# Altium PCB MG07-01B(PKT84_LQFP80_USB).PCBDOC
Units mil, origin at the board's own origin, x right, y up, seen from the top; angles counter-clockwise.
Board outline 2755.91 x 2755.91 mil, 2 copper layers (Top Layer, Bottom Layer); 70 components, 99 nets, 341 pads, 159 vias.
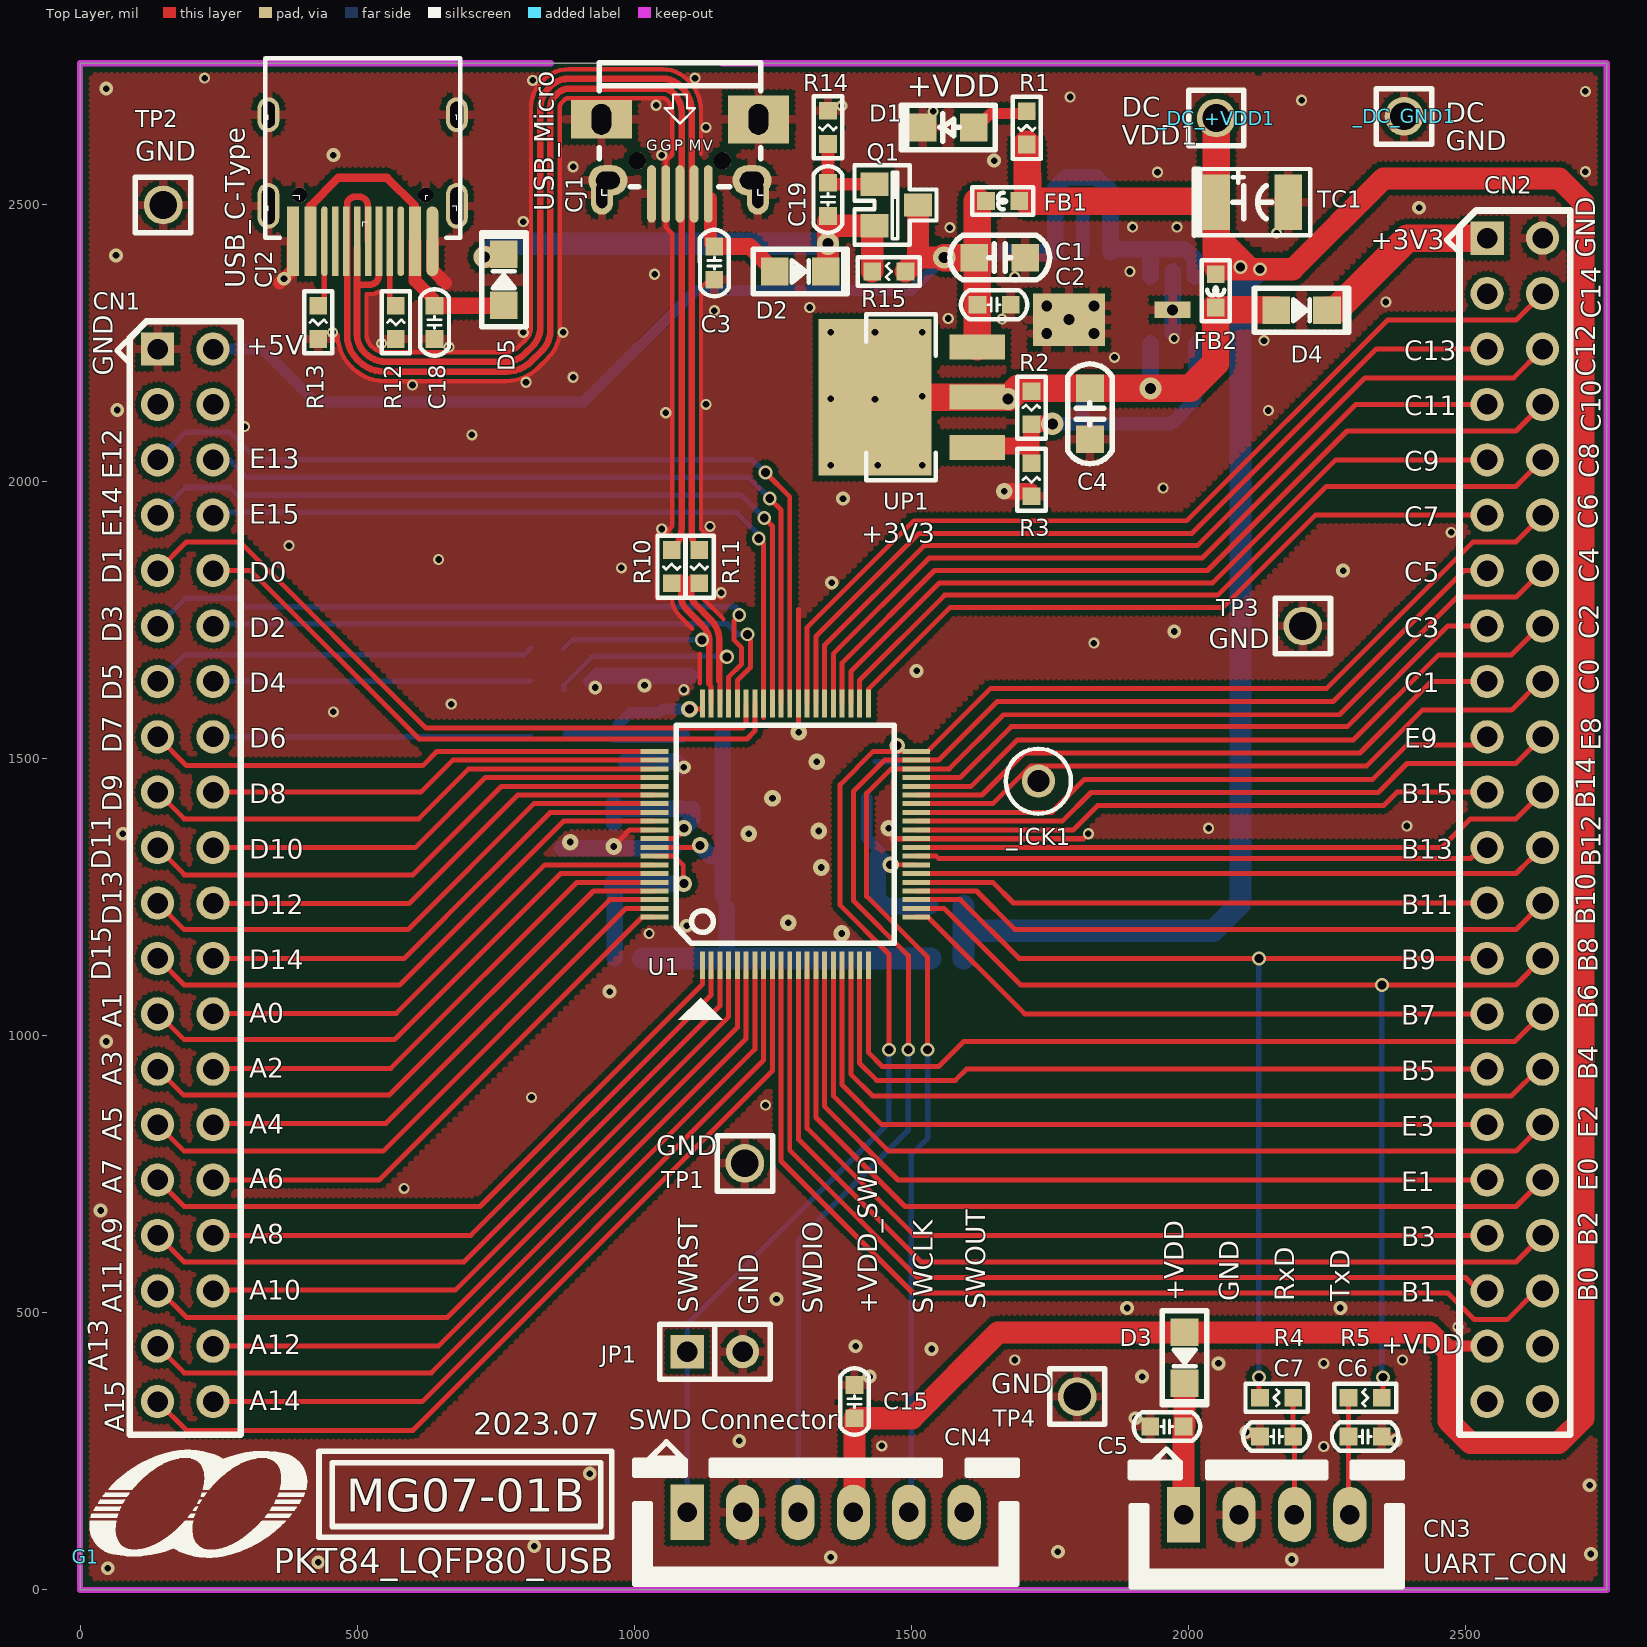
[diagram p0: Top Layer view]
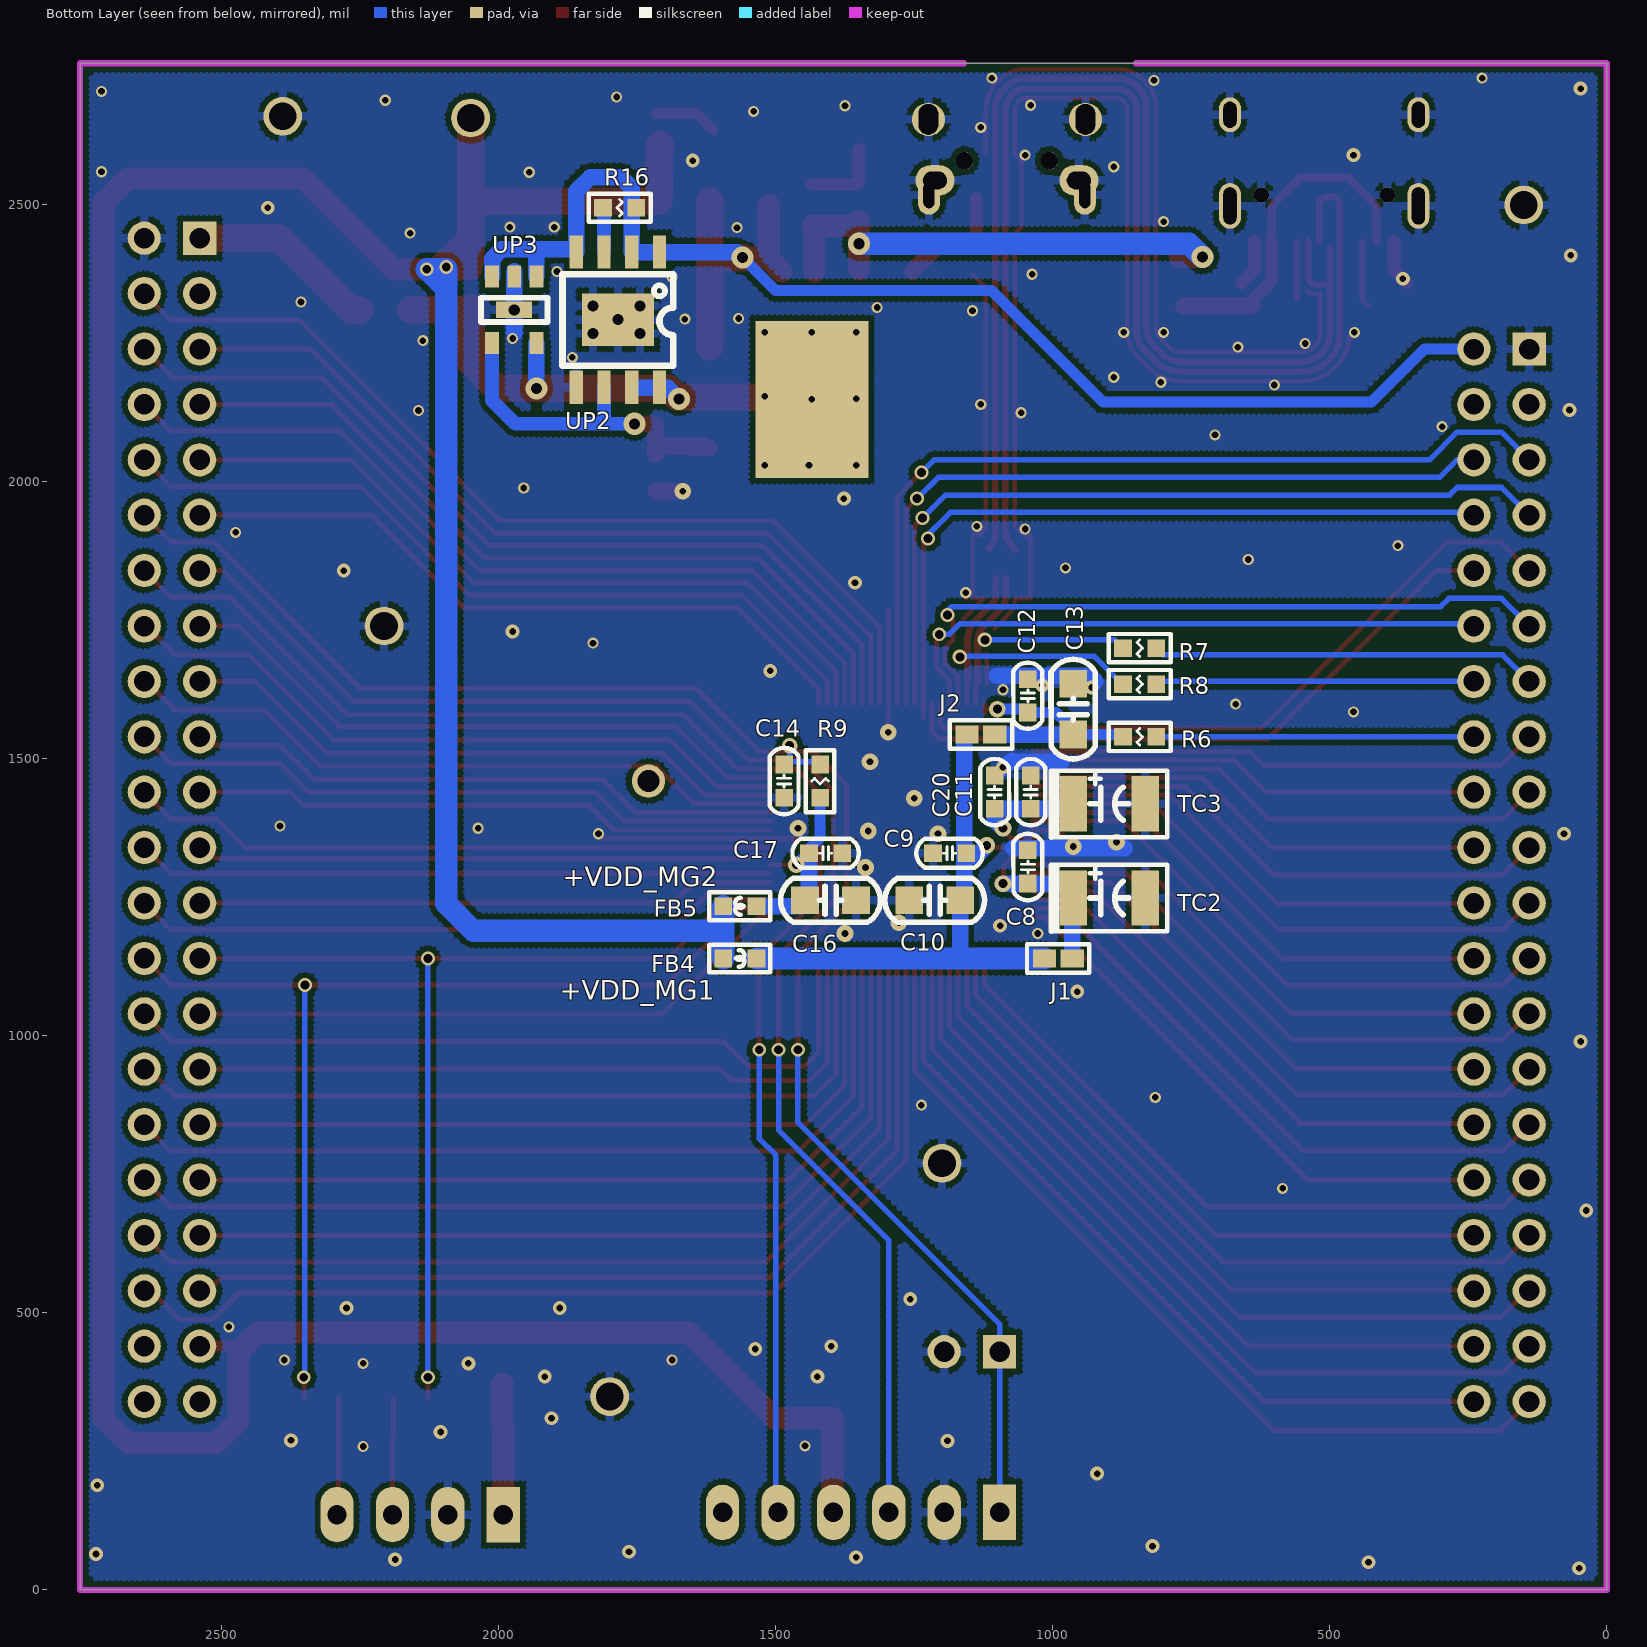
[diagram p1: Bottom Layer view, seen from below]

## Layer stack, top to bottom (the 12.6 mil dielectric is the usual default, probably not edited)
Top Layer: signal copper 1.4
Dielectric: dielectric 12.6, FR-4, Dk 4.8
Bottom Layer: signal copper 1.4

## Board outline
0,0 2755.91,0 2755.91,2755.91 0,2755.91

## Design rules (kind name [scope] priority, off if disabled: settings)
Clearance 10 [All] p1 off: gap=10
Clearance 7 [All] p2 off: gap=7
Clearance 6 [All] p3: gap=6
HoleSize [All] p1 off: absolutevalues=TRUE maxlimit=100 minlimit=1 maxpercent=80.000 minpercent=20.000
MinimumSolderMaskSliver [All] p1 off: minsoldermaskwidth=10
PolygonConnect +5V_USB [InNet('+5V_USB')] p1: connectstyle=Direct reliefconductorwidth=10 reliefentries=4 polygonreliefangle="90 Angle"
PolygonConnect via [isvia] p2: connectstyle=Direct reliefconductorwidth=10 reliefentries=4 polygonreliefangle="90 Angle"
PolygonConnect PolygonConnect_1 [All] p3: connectstyle=Relief reliefconductorwidth=15 reliefentries=4 polygonreliefangle="90 Angle"
RoomDefinition 02 [InComponentClass('02')] p1: confinementstyle=ConfineIn formatcopy=TRUE lockcomponents=FALSE outline -145,-65 2900,-65 2900,2850 -145,2850
RoomDefinition 01 [InComponentClass('01')] p2: confinementstyle=ConfineIn formatcopy=TRUE lockcomponents=FALSE outline -305,-15 2985,-15 2985,2795 -305,2795
RoutingVias [All] p1: holewidth=16 width=25 viastyle="Through Hole" minholewidth=16 minwidth=25 maxholewidth=28 maxwidth=50
SilkToSilkClearance [All] p1 off: silktosilkclearance=10
SilkscreenOverComponentPads [All] p1 off: minsilkscreentomaskgap=10
SolderMaskExpansion [All] p1: expansion=4
Width [All] p1: maxlimit=100 minlimit=6 preferedwidth=12
24 further rules are at their usual default settings.

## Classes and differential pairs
component class 02: _ICK1 C8 C9 C10 C11 C12 C13 C14 C15 C16 C17 C20 CN4 FB4 FB5 J1 J2 JP1 R6 R7 R8 R9 R10 R11 TC2 TC3 U1
component class 01: _DC_+VDD1 _DC_GND1 C1 C2 C3 C4 C5 C6 C7 C18 C19 CJ1 CJ2 CN1 CN2 CN3 D1 D2 D3 D4 D5 FB1 FB2 G1 Q1 R1 R2 R3 R4 R5 R12 R13 R14 R15 R16 TC1 TP1 TP2 TP3 TP4 UP1 UP2 UP3
net class MG_PE[0..15]: MG_PE0 MG_PE1 MG_PE2 MG_PE3 MG_PE8 MG_PE9 MG_PE12 MG_PE13 MG_PE14 MG_PE15
net class MG_PD[0..15]: MG_PD0 MG_PD1 MG_PD2 MG_PD3 MG_PD4 MG_PD5 MG_PD6 MG_PD7 MG_PD8 MG_PD9 MG_PD10 MG_PD11 MG_PD12 MG_PD13 MG_PD14 MG_PD15
net class MG_PC[0..14]: MG_PC0 MG_PC1 MG_PC2 MG_PC3 MG_PC4 MG_PC5 MG_PC6 MG_PC7 MG_PC8 MG_PC9 MG_PC10 MG_PC11 MG_PC12 MG_PC13 MG_PC14
net class MG_PB[0..15]: MG_PB0 MG_PB1 MG_PB2 MG_PB3 MG_PB4 MG_PB5 MG_PB6 MG_PB7 MG_PB8 MG_PB9 MG_PB10 MG_PB11 MG_PB12 MG_PB13 MG_PB14 MG_PB15
net class MG_PA[0..15]: MG_PA0 MG_PA1 MG_PA2 MG_PA3 MG_PA4 MG_PA5 MG_PA6 MG_PA7 MG_PA8 MG_PA9 MG_PA10 MG_PA11 MG_PA12 MG_PA13 MG_PA14 MG_PA15

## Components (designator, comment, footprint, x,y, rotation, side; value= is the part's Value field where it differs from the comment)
_DC_+VDD1 "+5V_DC" SIP1-50 2050.91,2657 r0 top
_DC_GND1 "GND" SIP1-50 2390,2660 r0 top
_ICK1 "TP-COIL" TPH60-COIL 1730,1460 r0 top
C1 "10uF/10v" C-0805 1660,2405 r0 top
C2 "0.1uF" C-0603 1650,2320 r0 top
C3 "1uF" C-0603 1145,2395 r270 top
C4 "10uF/10v" C-0805 1822.91,2123 r270 top
C5 "0.1uF" C-0603 1961.8,294.94 r180 top
C6 "47PF" C-0603 2319.8,276.94 r0 top
C7 "47PF" C-0603 2159.8,276.94 r180 top
C8 "0.1uF" C-0603 1045,1305 r90 bottom
C9 "0.1uF" C-0603 1186.2,1330 r0 bottom
C10 "10uF/10v" C-0805 1213.2,1245 r0 bottom
C11 "0.1uF" C-0603 1040,1440 r90 bottom
C12 "0.1uF" C-0603 1045,1614.06 r90 bottom
C13 "10uF/10v" C-0805 963.2,1590 r90 bottom
C14 "4.7uF" C-0603 1485,1460 r270 bottom
C15 "0.1uF" C-0603 1398,340 r90 top
C16 "10uF/10v" C-0805 1401.2,1245 r180 bottom
C17 "0.1uF" C-0603 1410,1330 r180 bottom
C18 "1uF" C-0603 640,2288 r270 top
C19 "0.1uF" C-0603 1350,2510 r90 top
C20 "1000pF" C-0603 1105,1440 r90 bottom
CJ1 "CJ-USB-Micro" USB5B-MICRO-7.5.X5.4P065 1134,2520 r180 top
CJ2 "CJ-USB3-C16P" USB16-C-C16P 510.08,2470 r180 top
CN1 "HEADER20X2-2.54-Female" HD20X2-P2.54 140,2240 r270 top locked
CN2 "HEADER22X2-2.54-Female" HD22X2-P2.54 2540,2440 r270 top locked
CN3 "SIP4-2.54mm" HD4-P2.54-Z12.4X5.7X7-UL 2142,136 r0 top
CN4 "SIP6-2.54mm" HD6-P2.54-UL 1346,140 r0 top
D1 "LED0805-Red" LED-0805 1565.32,2640 r270 top
D2 "B5817" D-0805 1300,2380 r90 top
D3 "B5817" D-0805 1993.8,418.94 r0 top
D4 "B5817" D-0805 2205,2310 r90 top
D5 "B5817" D-0805 765,2365 r180 top
FB1 "FB_0805" L-0603 1665.32,2507 r0 top
FB2 "FB_0805" L-0603 2050,2345 r90 top
FB4 "FB_0603" L-0603 1565,1140 r0 bottom
FB5 "FB_0603" L-0603 1565,1234.06 r180 bottom
G1 "Logo_Megawin10+Text" MEGAWIN_4.9_LOGO 10,60 r0 top
J1 "JUNCTION_0603" JUNCTION-0603 990,1140 r0 bottom
J2 "JUNCTION_0603" JUNCTION-0603 1130,1544.06 r180 bottom
JP1 "JUMPER" SIP2-P2.54 1096,430 r0 top
Q1 "IRLML6402" SOT-23 1470,2500 r90 top
R1 "2K" R-0603 1708.91,2639 r90 top
R2 "180" R-0603 1717.32,2134 r270 top
R3 "300" R-0603 1717.32,2004 r270 top
R4 "22" R-0603 2159.8,346.94 r180 top
R5 "22" R-0603 2319.8,346.94 r0 top
R6 "0" R-0603 843.2,1540 r180 bottom
R7 "0" R-0603 843.2,1700 r180 bottom
R8 "0" R-0603 843.2,1635 r180 bottom
R9 "47K" R-0603 1420,1460 r270 bottom
R10 "0" R-0603 1067.91,1847 r90 top
R11 "0" R-0603 1117.91,1847 r90 top
R12 "5.1K" R-0603 570,2288 r270 top
R13 "5.1K" R-0603 430,2288 r270 top
R14 "1M" R-0603 1350,2640 r90 top
R15 "0" R-0603 1460,2380 r0 top
R16 "100K" R-0603 1782,2495 r0 bottom
TC1 "10uF/10v" C-1210+ 2115.91,2505 r0 top
TC2 "10uF/10v" C-1210+ 898.2,1249.06 r180 bottom
TC3 "10uF/10v" C-1210+ 898.2,1419.06 r180 bottom
TP1 "TP-Gold" SIP1-50 1200,770 r0 top
TP2 "TP-Gold" SIP1-50 150,2500 r0 top
TP3 "TP-Gold" SIP1-50 2207.2,1740 r0 top
TP4 "TP-Gold" SIP1-50 1800,349.06 r0 top
U1 "JA243_LQFP80" QFP80-P0.4-Z12X12 1273.2,1364.06 r0 top locked
UP1 "AP1117-ADJ" SOT223H\3P 1491.32,2153 r90 top locked
UP2 "AP7165-ADJ" SOP8-P1.27-W6.2-PAD 1785,2293 r0 bottom
UP3 "AP7331-ADJ" SOT-25-PAD 1972.16,2310.75 r0 bottom

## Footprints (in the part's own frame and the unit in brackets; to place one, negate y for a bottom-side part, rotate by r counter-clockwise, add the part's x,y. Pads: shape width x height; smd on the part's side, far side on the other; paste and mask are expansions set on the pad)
C-0603 [mil]
  rect 32x32 smd: 1(-30,0) 2(30,0)
  silkscreen extent -60,-26 60,26
C-0805 [mil]
  rect 50x50 smd: 1(-46,0) 2(46,0)
  silkscreen extent -90,-40 90,40
C-1210+ [mil]
  rect 50x100 smd: 1(-65,0) 2(65,0)
  silkscreen extent -105,-60 105,60
D-0805 [mil]
  rect 50x50 smd: 1(0,46) 2(0,-46)
  silkscreen extent -40,-85 40,85
HD4-P2.54-Z12.4X5.7X7-UL [mil]
  rect 60x100 hole 35: 1(-150,0)
  oval 60x100 hole 35: 2(-50,0) 3(50,0) 4(150,0)
  silkscreen extent -246,-130 245,118
HD6-P2.54-UL [mil]
  rect 60x100 hole 35: 1(-250,0)
  oval 60x100 hole 35: 2(-150,0) 3(-50,0) 4(50,0) 5(150,0) 6(250,0)
  silkscreen extent -344,-130 346,127
HD20X2-P2.54 [mil]
  rect 60x60 hole 37: 1(0,0)
  round 60 hole 37: 2(0,100) 3(100,0) 4(100,100) 5(200,0) 6(200,100) 7(300,0) 8(300,100) 9(400,0) 10(400,100) 11(500,0) 12(500,100) 13(600,0) 14(600,100) 15(700,0) 16(700,100) 17(800,0) 18(800,100) 19(900,0) 20(900,100) 21(1000,0) 22(1000,100) 23(1100,0) 24(1100,100) 25(1200,0) 26(1200,100) 27(1300,0) 28(1300,100) 29(1400,0) 30(1400,100) 31(1500,0) 32(1500,100) 33(1600,0) 34(1600,100) 35(1700,0) 36(1700,100) 37(1800,0) 38(1800,100) 39(1900,0) 40(1900,100)
  silkscreen extent -50,-73 1960,150
HD22X2-P2.54 [mil]
  rect 60x60 hole 37: 1(0,0)
  round 60 hole 37: 2(0,100) 3(100,0) 4(100,100) 5(200,0) 6(200,100) 7(300,0) 8(300,100) 9(400,0) 10(400,100) 11(500,0) 12(500,100) 13(600,0) 14(600,100) 15(700,0) 16(700,100) 17(800,0) 18(800,100) 19(900,0) 20(900,100) 21(1000,0) 22(1000,100) 23(1100,0) 24(1100,100) 25(1200,0) 26(1200,100) 27(1300,0) 28(1300,100) 29(1400,0) 30(1400,100) 31(1500,0) 32(1500,100) 33(1600,0) 34(1600,100) 35(1700,0) 36(1700,100) 37(1800,0) 38(1800,100) 39(1900,0) 40(1900,100) 41(2000,0) 42(2000,100) 43(2100,0) 44(2100,100)
  silkscreen extent -50,-73 2160,150
JUNCTION-0603 [mil]
  rect 42x32 smd: 1(-25,0) 2(25,0)
  silkscreen extent -56,-26 57,26
L-0603 [mil]
  rect 32x32 smd: 1(-30,0) 2(30,0)
  silkscreen extent -55,-25 55,25
LED-0805 [mil]
  rect 50x50 smd: 1(0,48) 2(0,-44)
  silkscreen extent -40,-83 40,87
MEGAWIN_4.9_LOGO [mil]
  silkscreen extent 7,-1 400,192
QFP80-P0.4-Z12X12 [mm]
  rect 0.229x1.27 smd: 1(-3.8,-6) 2(-3.4,-6) 3(-3,-6) 4(-2.6,-6) 5(-2.2,-6) 6(-1.8,-6) 7(-1.4,-6) 8(-1,-6) 9(-0.6,-6) 10(-0.2,-6) 11(0.2,-6) 12(0.6,-6) 13(1,-6) 14(1.4,-6) 15(1.8,-6) 16(2.2,-6) 17(2.6,-6) 18(3,-6) 19(3.4,-6) 20(3.8,-6) 41(3.8,6) 42(3.4,6) 43(3,6) 44(2.6,6) 45(2.2,6) 46(1.8,6) 47(1.4,6) 48(1,6) 49(0.6,6) 50(0.2,6) 51(-0.2,6) 52(-0.6,6) 53(-1,6) 54(-1.4,6) 55(-1.8,6) 56(-2.2,6) 57(-2.6,6) 58(-3,6) 59(-3.4,6) 60(-3.8,6)
  rect 1.27x0.229 smd: 21(6,-3.8) 22(6,-3.4) 23(6,-3) 24(6,-2.6) 25(6,-2.2) 26(6,-1.8) 27(6,-1.4) 28(6,-1) 29(6,-0.6) 30(6,-0.2) 31(6,0.2) 32(6,0.6) 33(6,1) 34(6,1.4) 35(6,1.8) 36(6,2.2) 37(6,2.6) 38(6,3) 39(6,3.4) 40(6,3.8) 61(-6,3.8) 62(-6,3.4) 63(-6,3) 64(-6,2.6) 65(-6,2.2) 66(-6,1.8) 67(-6,1.4) 68(-6,1) 69(-6,0.6) 70(-6,0.2) 71(-6,-0.2) 72(-6,-0.6) 73(-6,-1) 74(-6,-1.4) 75(-6,-1.8) 76(-6,-2.2) 77(-6,-2.6) 78(-6,-3) 79(-6,-3.4) 80(-6,-3.8)
  silkscreen extent -5,-5 5,5
R-0603 [mil]
  rect 32x32 smd: 1(-30,0) 2(30,0)
  silkscreen extent -56,-26 56,26
SIP1-50 [mil]
  round 70 hole 50: 1(0,0)
  silkscreen extent -50,-50 50,50
SIP2-P2.54 [mil]
  rect 60x60 hole 37: 1(0,0)
  round 60 hole 37: 2(100,0)
  silkscreen extent -50,-50 150,50
SOP8-P1.27-W6.2-PAD [mil]
  rect 24x60 smd: 1(-75,-122) 2(-25,-122) 3(25,-122) 4(75,-122) 5(75,122) 6(25,122) 7(-25,122) 8(-75,122)
  rect 129.92x94.49 hole 19.68: 9(0,0)
  round 39.37 hole 19.68: 10(-40,25) 11(45,25) 12(-40,-25) 13(45,-25)
  silkscreen extent -100,-82 100,83
SOT223H\3P [mil]
  rect 283x204 smd far side: 0(-3.94,56.32)
  rect 45x100 smd: 1(-91,-128) 2(0,-128) 3(91,-128)
  rect 283x204 smd: 4(0,56)
  silkscreen extent -150,-53 150,72
SOT-23 [mil]
  rect 42x50 smd: 1(37.4,36) 2(-37.4,36) 3(0,-42.74)
  silkscreen extent -72,-76 72,72
SOT-25-PAD [mil]
  rect 25x40 smd: 1(-40,-60) 2(0,-60) 3(40,-60) 4(40,60) 5(-40,60)
  rect 65x30 hole 20: 6(0,0)
  silkscreen extent -60,-22 60,22
TPH60-COIL [mil]
  round 60 hole 40: 1(0,0)
  silkscreen extent -59,-59 59,59
USB5B-MICRO-7.5.X5.4P065 [mm]
  oval 0.4x2.632 smd: 1(0,0) 2(0.65,0) 3(1.3,0) 4(1.95,0) 5(2.6,0)
  oval 1.8x1.4 hole 0.8 slot 1.1 at 0 deg: 6(4.6,-0.619) 9(-2,-0.619)
  oval 1x1.8 hole 0.5 slot 1.2 at 90 deg: 6(4.875,0.051) 9(-2.275,0.051)
  rect 2.8x1.778 / inner round 1.524 / far side round 1.524 hole 0.9 slot 1.4 at 90 deg: 7(4.9,-3.419)
  rect 2.8x2.2 / inner round 1.524 / far side round 1.524 hole 0.9 slot 1.4 at 90 deg: 8(-2.3,-3.419)
  round 0.8 hole 0.8 unplated: 10(-0.65,-1.519) 11(3.25,-1.519)
  silkscreen extent -2.53,-6.02 5,0.05
USB16-C-C16P [mm]
  oval 0.55x3.2 smd: A1(-3.2,0.9)
  rect 0.55x3.2 smd: A4(-2.4,0.9) A9(2.4,0.9) A12(3.2,0.9)
  rect 0.3x3.2 smd: A5(-1.25,0.9) A6(-0.25,0.9) A7(0.25,0.9) A8(1.25,0.9) B6(0.75,0.9) B7(-0.75,0.9)
  oval 0.3x3.2 smd: B5(1.75,0.9) B8(-1.75,0.9)
  oval 1x2.1 hole 0.6 slot 1.7 at 90 deg: M1(-4.32,-0.718) M2(4.32,-0.718)
  oval 1x1.6 hole 0.6 slot 1.2 at 90 deg: M3(4.32,-4.898) M4(-4.32,-4.898)
  round 0.7 hole 0.7 unplated: M5(-2.89,-1.218) M6(2.89,-1.218)
  silkscreen extent -4.48,-7.5 4.55,0.74

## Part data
_DC_+VDD1 _DC_GND1 TP1 TP2 TP3 TP4: library part TPH-GND
_ICK1: library part TPH60-COIL
C1 C4 C10 C13 C16: library part CAP-POL
C2 C3 C5 C6 C7 C8 C9 C11 C12 C14 C15 C17 C18 C19 C20: library part CAP-NP
CJ2: "TPYE-C-9"
CN1: library part HEADER20X2
CN2: library part HEADER22X2
CN3: library part SIP4
CN4: library part SIP6
D1: library part LED
D2 D3 D4 D5: library part DIODE-SCHOTTKY-2
FB1 FB2 FB4 FB5: library part FB2
G1: library part LOGO-Megawin10+Text
Q1: library part MOS-P-SOT23
R1 R2 R3 R4 R5 R6 R7 R8 R9 R10 R11 R12 R13 R14 R15 R16: library part R
TC1 TC2 TC3: library part CAP-EC
U1: library part IC-MG32F02A128-LQFP80
UP1: library part ICP-AP1117
UP2: library part ICP-AP7165
UP3: library part SOT25-PAD

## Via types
v1: diameter 20, hole 12, Top Layer to Bottom Layer, tented both sides, 52 vias
v2: diameter 25, hole 12, Top Layer to Bottom Layer, tented both sides, 50 vias
v3: diameter 20, hole 12, Top Layer to Bottom Layer, 16 vias
v4: diameter 25, hole 16, Top Layer to Bottom Layer, tented both sides, 15 vias
v5: diameter 30, hole 12, Top Layer to Bottom Layer, tented both sides, 12 vias
v6: diameter 40, hole 20, Top Layer to Bottom Layer, tented both sides, 6 vias
v7: diameter 30, hole 16, Top Layer to Bottom Layer, tented both sides, 5 vias
v8: diameter 26, hole 16, Top Layer to Bottom Layer, tented both sides, 2 vias
v9: diameter 28, hole 16, Top Layer to Bottom Layer, tented both sides, 1 vias

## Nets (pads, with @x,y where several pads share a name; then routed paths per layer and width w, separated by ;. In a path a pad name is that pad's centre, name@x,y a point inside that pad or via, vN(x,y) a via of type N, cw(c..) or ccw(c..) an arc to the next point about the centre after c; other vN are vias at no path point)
+3V3: CN2.1 D4.2 | length 342.8
  Top Layer w50: D4.2 2266,2310 2396,2440 CN2.1
+3V3_LDO: C4.1 D4.1 FB2.1 R2.1 UP1.0 UP1.2 UP1.4 UP2.7 UP2.8 UP3.5 | length 1019.4
  Top Layer w50: UP1.4 UP1.2 1678,2153 1694,2169 C4.1 v6(1932.16,2169) 2004,2169 2050,2215 FB2.1@2050,2310.75 ; FB2.1 FB2.1@2050,2310.75 ; D4.1@2159,2310.75 FB2.1@2050,2310.75
  Bottom Layer w30: v6(1675,2150) 1695,2170 UP2.7@1755,2170 ; v6(1932.16,2169) UP3.5
  other v2: 1355,2030 1440,2030 1520,2030 1435,2149.06 1355,2150 1520,2155 1355,2270 1435,2270 1520,2270
+5V: C1.1 C2.1 CN1.2 FB1.1 Q1.3 R15.2 R16.1 UP1.3 UP2.1 UP2.2 UP2.4 UP3.1 UP3.3 | length 2751.9
  Top Layer w40: R15.2 1507.74,2397.74 ; Q1.3 1512.74,2405 v6(1560,2405)
  Top Layer w50: CN1.2 CN1.2@244,2244 ; v6(1560,2405) C1.1 C1.1@1619.32,2405 ; UP1.3 C1.1@1619.32,2405 ; FB1.1@1619.32,2507 C1.1@1619.32,2405
  Bottom Layer w20: CN1.2 329,2240 425,2144 909,2144 1110.79,2345.79 1500.79,2345.79 v6(1560,2405)
  Bottom Layer w30: v6(1560,2405) 1570,2415 UP2.1 UP2.2 1760,2530.59 1779.41,2550 1835,2550 1860,2525 UP2.4@1860,2420 ; UP2.4 UP2.4@1860,2420 ; UP3.1 1932.16,2420 ; UP3.3 2012.16,2402.84 1995,2420 1932.16,2420 ; UP2.4@1860,2420 1932.16,2420
+5V_UP: C19.1 D2.2 D5.2 Q1.2 R15.1 | length 911.1
  Top Layer w40: v6(730,2406) D5.2@770,2406 ; D2.2@1350,2384 v6(1350,2430) C19.1@1350,2470 ; 1357.4,2462.6 Q1.2 ; R15.1 Q1.2@1430,2458.6
  Bottom Layer w40: v6(730,2406) 754,2430 v6(1350,2430)
+5V_USB: C3.1 CJ1.1 D2.1 | length 209.6
  Top Layer w23: C3.1@1138,2430 CJ1.1@1138,2512
  Top Layer w30: C3.1 1209,2425 D2.1
+5V_USB3: C18.1 CJ2.A4 CJ2.A9 D5.1 | length 607.1
  Top Layer w15: CJ2.A9 415.57,2498.57 466,2549 554.25,2549 604.58,2498.66 CJ2.A4
  Top Layer w23: CJ2.A4 604.58,2363.42 637.5,2330.5 637.5,2327.5 C18.1@640,2325
  Top Layer w30: C18.1 D5.1@764,2318
+V33_MG: C12.1 C13.1 J2.2 R6.1 U1.60 | length 386.7
  Top Layer w9: v7@1096.8,1590 v7(1100,1590) U1.60@1120,1590 ; U1.60@1123.2,1584 U1.60
  Bottom Layer w20: R6.1@881.2,1544.06 C13.1@963.2,1544.06 ; C13.1@970,1560 994.06,1584.06 C12.1 1050.94,1590 v7(1100,1590)
  Bottom Layer w30: C13.1@963.2,1544.06 J2.2@1085.94,1544.06
+VDD: _DC_+VDD1.1 C15.1 CN2.41 CN4.4 D3.1 FB1.2 FB2.2 FB4.2 FB5.1 R1.1 TC1.1 | length 7471.1
  Top Layer w20: 2460,440 CN2.41
  Top Layer w30: 2045.5,2443.5 2050.91,2438.09 v4@2105,2384 ; 2052.5,2452.5 2121,2384 v4@2125.5,2379.5
  Top Layer w40: CN4.4 1398,142 C15.1 1502.2,310 1657.15,464.94 D3.1 2435.06,464.94 2460,440 2470,430 2470,305 2510,265 2669,265 2714,310 2714,2504 2670,2548 2353,2548 2189,2384 v4(2130,2384) 2121,2384 2105,2384 FB2.2@2050,2384
  Top Layer w50: R1.1 1711.31,2507.38 1711.31,2507 2050.91,2507 _DC_+VDD1.1 ; 2050.91,2401.6 2050.91,2438.09 TC1.1
  Bottom Layer w40: FB4.2 FB5.1 ; 1600,1190 2046,1190 2095,1239 2095,2349 ; 2095,2349 v4(2130,2384) 2095,2384 2095,2349
  other v4: 2095,2388
+VDD_MG1: C9.1 C10.1 FB4.1 J1.2 J2.1 U1.72 | length 1021
  Top Layer w9: U1.72 1105.58,1340.43 v7@1109.2,1344.06
  Bottom Layer w30: v7(1119.2,1344.06) 1139.2,1324.06 C9.1@1156.2,1324.06 ; C10.1@1160,1251.06 J2.1@1160,1544.06 ; 1167.2,1142.06 C10.1@1167.2,1231.06
  Bottom Layer w40: J1.2 FB4.1
+VDD_MG2: C16.1 C17.1 FB5.2 R9.2 U1.27 | length 363.2
  Top Layer w9: v7(1463.2,1309.06) U1.27
  Bottom Layer w20: R9.2 1420,1357.14 C17.1@1443.57,1333.57 ; C17.1@1437.44,1328.54 1440,1324.06 1448.09,1324.06 v7(1463.2,1309.06)
  Bottom Layer w30: C17.1@1440,1324.06 1440,1249.06 1455,1234.06 FB5.2
+VDD_UART0: C5.1 CN3.1 D3.2 | length 237.8
  Top Layer w40: CN3.1 1992,279.15 C5.1 1993.8,296.94 D3.2
GND: _DC_GND1.1 C1.2 C2.2 C3.2 C4.2 C5.2 C6.2 C7.2 C8.2 C9.2 C10.2 C11.2 C12.2 C13.2 C14.2 C15.2 C16.2 C17.2 C18.2 C20.2 CJ1.4 CJ1.5 CJ1.6 CJ1.7 CJ1.8 CJ1.9 CJ2.A1 CJ2.A12 CJ2.M1 CJ2.M2 CJ2.M3 CJ2.M4 CJ2.M5 CJ2.M6 CN1.1 CN2.2 CN3.2 CN4.2 D1.2 JP1.2 R3.2 R12.2 R13.2 R14.2 TC1.2 TC2.2 TC3.2 TP1.1 TP2.1 TP3.1 TP4.1 U1.30 U1.49 U1.70 UP2.5 UP2.9 UP2.10 UP2.11 UP2.12 UP2.13 UP3.2 UP3.6 | length 5782.4
  Top Layer w8: v1@450,2269.06 465,2254.06 465,2265.24 ccw(c544.04,2265.24) 488.15,2209.35 491.09,2206.41 ccw(c550,2265.28) 550,2182 769.01,2182 ; 526.04,2245 cw(c548.03,2266.89) 517,2266.89 517,2339.13 521.54,2339.13 ccw(c522.88,2372.29) 539.92,2343.81 ; 526.09,2244.95 ccw(c552.53,2271.4) 552.53,2234 767.51,2234 ccw(c767.51,2267.79) 791.4,2243.9 804.45,2256.94 ; 761.95,2182 769.01,2182 ; 804.49,2256.98 ccw(c781.4,2280) 814,2280 814,2677 cw(c876.87,2677) 832.38,2721.42 ; 827.11,2206.06 cw(c769.01,2264.16) 769.01,2182 ; 827.13,2206.08 845.5,2224.46 ccw(c796.08,2273.92) 866,2273.92 866,2676.65 cw(c877.71,2676.65) 869.43,2684.93 873.59,2689.09 ; 832.45,2721.5 837.7,2726.74 ; 837.76,2726.8 cw(c881.75,2682.73) 881.75,2745 1052.19,2745 cw(c1052.19,2683.91) 1095.35,2727.15 ; 873.64,2689.14 cw(c883,2679.72) 883,2693 1051.85,2693 cw(c1051.85,2683.07) 1058.84,2690.12 ; 1040.91,1844 1040.91,1790 ; 1059.68,2689.28 cw(c1037.39,2667) 1068.91,2667 1068.91,2590.91 1057.23,2579.23 1057.23,2459.77 1068.91,2448.09 1068.91,1920.06 1052.85,1904 1040.91,1904 1040.91,1790 ; 1059.81,1790 1040.91,1790 ; 1082.72,1757.79 cw(c1118.36,1793.36) 1068.11,1790 1040.91,1790 ; 1082.77,1757.73 1105.25,1735.25 ; 1095.41,2727.09 1098.55,2723.95 ; 1098.6,2723.9 cw(c1044.64,2670) 1120.91,2670 1120.91,2592 ; 1118.91,1637 1118.91,1690 ; 1144.91,1802.3 1157.2,1790 ; C3.2@1145,2375 1120.91,2350.91 1120.91,1915 1131.91,1904 1144.91,1904 1144.91,1790 1124.04,1790 1161.52,1752.52
  Top Layer w9: v5(963.2,1342.06) 991.93,1371.93 U1.70 ; 1296.83,1770 1296.83,1548.43 v5(1297.2,1548.06)
  Top Layer w10: 1466.08,1356.18 1811.18,1356.18 v1(1820,1365)
  Top Layer w23: v2@360.16,2359.06 384.08,2382.98 CJ2.A12 ; CJ2.A1 636.08,2382.98 660,2359.06
  Top Layer w30: v5(1668,1983) R3.2@1716.32,1983
  Bottom Layer w30: 870,1339.05 1071,1339.05 ; 923.2,1640 933.2,1650 1101.1,1650 ; 985,1495 1076.1,1495 ; 1074.2,1497.06 v2@1087.2,1484.06 ; 1972.16,2269.06 UP3.2@1972.16,2380
  other v1: 2245,259.06 1447.2,260 2245,409.06 1687.2,415 2387.2,415 2487.2,475 585,725 1237.2,875 815,889.06 1027.2,1185 2037.2,1375 2395,1379.06 457.2,1585 670,1599.06 1090,1625 1830,1709.06 1157.2,1800 977.2,1845 647.2,1860 377.2,1885 2475,1909.06 1050,1915 1137.2,1920 1955,1989.06 707.2,2085 297.2,2100 1057.2,2125 1130,2140 600,2175 805,2180 890,2189.06 666.01,2243.35 544.41,2250 455.59,2270 800,2270 872,2270 1567.2,2295 1145,2309.06 1317.2,2315 1037.2,2375 1570,2459.06 800,2470 890,2569.06 1050,2590 1130,2640 1540,2669.06 1375,2679.06 1040,2680 817.2,2725 225,2729.06 1110,2729.06
  other v2: 50,39.06 430,50 2187.2,55 1355,59.06 2727.2,65 1765,69.06 820,79.06 2725,189.06 920,210 1190,269.06 2375,270 2105,285 1905,310 1425,385 1917.2,385 2055,409.06 1537.2,435 1400,440 1890,509.06 2275,509.06 1257.2,525 37.2,685 47.2,990 956,1080 1095,1199.06 77.2,1365 1090,1485 930,1629.06 1019.01,1632.78 1510,1659.06 1975,1730 1357,1818 2280,1840 1377.2,1970 67.2,2130 368.05,2366.94 65,2409 2417.2,2495 1650,2580 457.2,2590 47.2,2710
  other v3: 2145,2129.06 1867.2,2225 2137.2,2255 1975,2259.06 1664.08,2294.01 2357.2,2325 1687.2,2370 1895,2380 2160,2449.06 1900,2460 1980,2460 1945,2559.06 2717.2,2560 2205,2689.06 1787.2,2695 2717.2,2705
  other v5: 1375,1185 1278.2,1204.06 1338.2,1304.06 885,1350 1207.2,1365 1333.2,1370.06 1460,1375 1250,1429.06 1330,1495
LDO_ADJ: R2.2 R3.1 UP1.1 UP2.6 UP3.4 | length 643.4
  Top Layer w30: UP1.1 UP1.1@1652,2062 ; UP1.1@1627.2,2065 1717.32,2065 ; 1716.32,2050 1717.32,2049 1717.32,2065 ; R2.2 1717.32,2065 ; v6@1735,2105 v6(1755,2105)
  Bottom Layer w25: v6(1755,2105) 1810,2105 ; UP2.6 1810,2105 ; UP3.4 2012.16,2147.16 1970,2105 1810,2105
MG_DM: CJ1.2 CJ2.A7 CJ2.B7 R11.2 | length 2183.9
  Top Layer w12: CJ2.A7@500,2422 500,2356.13 ; CJ2.B7@538.91,2434.57 538.91,2370 cw(c522.88,2372.29) 521.95,2356.13 500,2356.13 ; 816.47,2244.93 803.42,2231.88 cw(c767.51,2267.79) 767.51,2217 552.53,2217 cw(c552.53,2271.4) 514.07,2232.93 cw(c548.03,2266.89) 500,2266.89 500,2356.13 ; 816.49,2244.94 ccw(c781.4,2280) 831,2280 831,2677 cw(c876.87,2677) 844.41,2709.41 ; 844.44,2709.43 849.74,2714.74 cw(c881.75,2682.73) 881.75,2728 1052.19,2728 cw(c1052.19,2683.91) 1083.34,2715.11 1086.55,2711.91 cw(c1044.64,2670) 1103.91,2670 1103.91,1907 ccw(c1142.53,1907) R11.2@1115.22,1879.69
MG_DP: CJ1.3 CJ2.A6 CJ2.B6 R10.2 | length 2276.9
  Top Layer w12: 502.26,2515.01 498.21,2515.01 ccw(c497.28,2498.84) 482,2504.2 482,2265.24 ccw(c544.04,2265.24) 500.17,2221.37 503.13,2218.41 ccw(c550,2265.28) 550,2199 760,2199 ; 504.13,2515.01 cw(c503.19,2498.84) 519.22,2501.13 CJ2.A6@519.22,2434.57 ; 761.95,2199 760,2199 ; 861.59,2701.13 857.41,2696.95 ccw(c877.71,2676.65) 849,2676.65 849,2273.92 cw(c796.08,2273.92) 833.5,2236.5 815.09,2218.09 cw(c769.01,2264.16) 769.01,2199 760,2199 ; 861.6,2701.14 cw(c883,2679.72) 883,2710 1051.85,2710 cw(c1051.85,2683.07) 1070.88,2702.12 ; R10.2 1071.07,1880.17 ccw(c1035.21,1916) 1085.91,1916 1085.91,2667 ccw(c1037.39,2667) 1071.7,2701.3 1070.89,2702.11
MG_PA0: CN1.26 U1.74 | length 908.4
  Top Layer w9: CN1.26 240.94,1040.94 570.94,1040.94 838.94,1308.94 U1.74
MG_PA1: CN1.25 U1.75 | length 1039.4
  Top Layer w9: CN1.25@141.19,1040 188,993.19 567.64,993.19 867.64,1293.19 U1.75
MG_PA2: CN1.28 U1.76 | length 936.8
  Top Layer w9: CN1.28 241.44,941.44 560.89,941.44 896.89,1277.44 U1.76
MG_PA3: CN1.27 U1.77 | length 1068.6
  Top Layer w9: CN1.27 186.31,893.69 558.69,893.69 926.69,1261.69 U1.77
MG_PA4: CN1.30 U1.78 | length 965.1
  Top Layer w9: CN1.30 241.94,841.94 551.94,841.94 955.94,1245.94 U1.78
MG_PA5: CN1.29 U1.79 | length 1098.4
  Top Layer w9: CN1.29 188,792 547,792 985.2,1230.2 U1.79
MG_PA6: CN1.32 U1.80 | length 993.5
  Top Layer w9: CN1.32 540,740 1014.45,1214.45 U1.80
MG_PA7: CN1.31 U1.1 | length 1204.1
  Top Layer w9: CN1.31 188,692 722,692 1123.6,1093.6 U1.1
MG_PA8: CN1.34 U1.2 | length 1133
  Top Layer w9: CN1.34 705.36,640 1139.35,1073.99 U1.2
MG_PA9: CN1.33 U1.3 | length 1300
  Top Layer w9: CN1.33 188,592 692.71,592 1155.09,1054.38 U1.3
MG_PA10: CN1.36 U1.4 | length 1228.8
  Top Layer w9: CN1.36 241.16,541.16 677.22,541.16 1170.84,1034.78 U1.4
MG_PA11: CN1.35 U1.5 | length 1391.8
  Top Layer w9: CN1.35@144,540 192,492 663.42,492 1186.59,1015.17 U1.5
MG_PA12: CN1.38 U1.6 | length 1324.7
  Top Layer w9: CN1.38 646.78,440 1202.34,995.56 U1.6
MG_PA13: CN1.37 U1.7 | length 1491.7
  Top Layer w9: CN1.37 188,392 634.13,392 1218.09,975.95 U1.7
MG_PA14: CN1.40 U1.8 | length 1420.6
  Top Layer w9: CN1.40 617.49,340 1233.83,956.35 U1.8
MG_PA15: CN1.39 U1.9 | length 1590.9
  Top Layer w9: CN1.39 192,288 600.84,288 1249.58,936.74 U1.9
MG_PB0: CN2.40 U1.10 | length 1868.3
  Top Layer w9: U1.10 1265.33,774.31 1503.64,536 2469,536 2517,488 2576,488 2628,540 CN2.40
MG_PB1: CN2.39 U1.11 | length 1698
  Top Layer w9: U1.11 1281.08,793.92 1511,564 2501,564 2525,540 CN2.39
MG_PB2: CN2.38 U1.12 | length 1769.1
  Top Layer w9: U1.12 1296.83,813.53 1518.36,592 2592,592 CN2.38
MG_PB3: CN2.37 U1.13 | length 1602.1
  Top Layer w9: U1.13 1312.57,833.14 1505.71,640 CN2.37
MG_PB4: CN2.32 U1.18 | length 1481.5
  Top Layer w9: U1.18 1391.31,931.17 1430.49,892 2584,892 2632,940 CN2.32
MG_PB5: CN2.31 U1.19 | length 1331
  Top Layer w9: U1.19 1407.06,950.78 1437.84,920 1580,920 1600,940 CN2.31
MG_PB6: CN2.30 U1.20 | length 1424.5
  Top Layer w9: U1.20 1422.81,970.39 1448.2,945 1550,945 1595,990 2590,990 CN2.30
MG_PB7: CN2.29 U1.21 | length 1102.8
  Top Layer w9: U1.21 1530.55,1214.45 1705,1040 CN2.29
MG_PB8: CN2.28 R5.2 U1.22 | length 1954.5
  Top Layer w9: U1.22 1559.8,1230.2 1698,1092 v4(2350,1092) 2592,1092 CN2.28 ; R5.2 2352,349.15 v4(2352,384)
  Bottom Layer w10: v4(2350,1092) 2350,386 v4(2352,384)
MG_PB9: CN2.27 R4.2 U1.23 | length 1868.3
  Top Layer w9: U1.23 1589.06,1245.94 1695,1140 v4(2128,1140) CN2.27 ; v4(2128,384) 2128,348.74 R4.2
  Bottom Layer w10: v4(2128,384) v4(2128,1140)
MG_PB10: CN2.26 U1.24 | length 1179.3
  Top Layer w9: U1.24 1618.31,1261.69 1688,1192 2592,1192 CN2.26
MG_PB11: CN2.25 U1.25 | length 1046.1
  Top Layer w9: U1.25 1647.56,1277.44 1685,1240 CN2.25
MG_PB12: CN2.24 U1.26 | length 1150
  Top Layer w9: U1.26 2592,1293.19 2616.81,1318 2618,1318 CN2.24
MG_PB13: CN2.23 U1.28 | length 1040.8
  Top Layer w9: U1.28 1545.32,1324.68 1550,1320 2510,1320 2530,1340 CN2.23
MG_PB14: CN2.22 U1.29 | length 1171.8
  Top Layer w9: U1.29 2458.43,1340.43 2510,1392 2592,1392 CN2.22
MG_PB15: CN2.21 U1.31 | length 1058.8
  Top Layer w9: U1.31 1792.64,1371.93 1836.46,1415.75 2352.92,1415.75 2377.17,1440 CN2.21
MG_PC0: _ICK1.1 CN2.18 U1.34 | length 1222
  Top Layer w9: U1.34 1647.64,1419.17 1715.46,1486.99 2321.99,1486.99 2423,1588 2584,1588 2636,1640 CN2.18
MG_PC1: CN2.17 U1.35 | length 1115.5
  Top Layer w9: U1.35 1628.04,1434.92 1703.86,1510.74 2310.38,1510.74 2439.64,1640 CN2.17
MG_PC2: CN2.16 U1.36 | length 1250.4
  Top Layer w9: U1.36 1608.43,1450.67 1692.25,1534.49 2298.78,1534.49 2452.29,1688 2584,1688 2636,1740 CN2.16
MG_PC3: CN2.15 U1.37 | length 1143.9
  Top Layer w9: U1.37 1588.82,1466.42 1680.64,1558.24 2287.17,1558.24 2468.93,1740 CN2.15
MG_PC4: CN2.14 CN4.5 U1.38 | length 2744.3
  Top Layer w9: v4(1530,975) 1530,1142 1420,1252 1420,1438.17 1464,1482.17 U1.38 1569.21,1482.17 1666.87,1579.82 2273.4,1579.82 2485.58,1792 2592,1792 CN2.14
  Bottom Layer w10: CN4.5 1500,144 1500,785 1530,815 v4(1530,975)
MG_PC5: CN2.13 CN4.3 U1.39 | length 2734.2
  Top Layer w9: v4(1495,975) 1495,1145 1396,1244 1396,1441.91 1452,1497.91 U1.39 1549.61,1497.91 1655.51,1603.82 2262.04,1603.82 2498.22,1840 CN2.13
  Bottom Layer w10: CN4.3 1296,631 1495,830 v4(1495,975)
MG_PC6: C14.1 CN2.12 CN4.1 JP1.1 R9.1 U1.40 | length 3061.9
  Top Layer w9: v4(1460,975) 1460,1148 1372,1236 1372,1453.66 1432,1513.66 U1.40 ; U1.40@1520,1513.66 U1.40 ; CN2.12 2592,1892 2514.87,1892 2249.69,1626.82 1643.16,1626.82 1530,1513.66 U1.40
  Bottom Layer w10: CN4.1 JP1.1 1096,480 1460,844 v4(1460,975) ; R9.1@1435,1495 C14.1@1470,1495 ; C14.1@1475,1485 v9(1475,1524) v9@1475,1530.94
MG_PC7: CN2.11 U1.41 | length 1273
  Top Layer w9: U1.41 1422.81,1626.05 1569.95,1773.19 2062.88,1773.19 2229.69,1940 CN2.11
MG_PC8: CN2.10 U1.42 | length 1439.5
  Top Layer w9: U1.42 1407.06,1641.94 1560.69,1795.56 2053.62,1795.56 2250.06,1992 2592,1992 CN2.10
MG_PC9: CN2.9 U1.43 | length 1364.5
  Top Layer w9: U1.43 1391.31,1657.83 1551.42,1817.93 2044.35,1817.93 2266.42,2040 CN2.9
MG_PC10: CN2.8 U1.44 | length 1530.8
  Top Layer w9: U1.44 1375.57,1673.43 1542.24,1840.1 2035.17,1840.1 2287.06,2092 2592,2092 CN2.8
MG_PC11: CN2.7 U1.45 | length 1456.2
  Top Layer w9: U1.45 1359.82,1689.76 1532.84,1862.78 2025.77,1862.78 2302.99,2140 CN2.7
MG_PC12: CN2.6 U1.46 | length 1622.6
  Top Layer w9: U1.46 1344.07,1705.65 1523.58,1885.15 2016.51,1885.15 2319.35,2188 2588,2188 CN2.6
MG_PC13: CN2.5 U1.47 | length 1547.5
  Top Layer w9: U1.47 1328.32,1721.25 1514.39,1907.32 2007.32,1907.32 2340,2240 CN2.5
MG_PC14: CN2.4 U1.48 | length 1714.3
  Top Layer w9: U1.48 1312.57,1737.57 1505,1930 1997.93,1930 2359.93,2292 2592,2292 CN2.4
MG_PD0: CN1.10 U1.54 | length 1159.9
  Top Layer w9: CN1.10 308,1840 612,1536 1203.75,1536 1218.09,1550.34 U1.54
MG_PD1: CN1.9 U1.55 | length 1263.6
  Top Layer w9: CN1.9 192,1892 288,1892 624,1556 1196,1556 1202.34,1562.34 U1.55
MG_PD2: CN1.12 U1.56 | length 1098
  Top Layer w9: U1.56 1186.59,1641.59 1210,1665 v4@1210,1714.06
  Bottom Layer w10: CN1.12 244,1744 1168.2,1744 1187.2,1725 v4(1205,1725)
MG_PD3: CN1.11 U1.57 | length 1268.4
  Top Layer w9: U1.57 1170.84,1648.11 1194.25,1671.52 1194.25,1700.75 1180,1715 1180,1749.06 v4@1190,1759.06
  Bottom Layer w10: CN1.11 190,1790 285,1790 300,1775 1183.2,1775 v4@1197.2,1761
  other v4: 1190,1760
MG_PD4: CN1.14 R8.2 | length 573.2
  Bottom Layer w10: CN1.14 R8.2@813.2,1640
MG_PD4X: R8.1 R11.1 U1.58 | length 592.1
  Top Layer w9: 1153.91,1641 1155.09,1641 U1.58
  Top Layer w9.62: 1153.91,1674.29 1155.09,1674.29
  Top Layer w12: R11.1@1103,1827 1103,1798 ; 1153.91,1641 1153.91,1674.29 1153.91,1716.25 ccw(c1153.72,1716.25) 1153.85,1716.38 ccw(c1100.56,1714) 1138.28,1751.72 1110.78,1779.22 ; 1103,1798 ccw(c1129.56,1798) 1110.78,1779.22 ; 1103,1798 ccw(c1129.56,1798) 1110.78,1779.22
  Bottom Layer w10: R8.1@873.2,1625 873.2,1633.2 925,1685 1166.83,1685 v8(1167.65,1684.18)
MG_PD5: CN1.13 R7.2 | length 698.1
  Bottom Layer w10: CN1.13 188,1688 801.2,1688 R7.2
MG_PD5X: R7.1 R10.1 U1.59 | length 613.2
  Top Layer w9: U1.59 1139.35,1630.65 1136,1634 ; 1135,1635 1136,1634 ; 1135,1635 1135,1636 1135.31,1635.69 ; 1135,1635 1135.31,1635.69 ; 1135.31,1635.69 1135.91,1637 1136.5,1634.5 ; 1135.31,1635.69 1136.5,1634.5 ; 1136,1634 1136.5,1634.5
  Top Layer w9.3: 1135,1636 1135.91,1637
  Top Layer w12: 1085,1827 1085,1793.36 ccw(c1118.36,1793.36) 1094.75,1769.79 ; 1094.77,1769.77 1123.77,1740.77 ; 1135.91,1637 1135.91,1711.48 ; 1135.91,1715 1135.91,1711.48 ; 1123.77,1740.77 cw(c1094.48,1711.48) 1135.91,1711.48 ; 1123.77,1740.77 cw(c1094.48,1711.48) 1135.91,1711.48 ; 1123.77,1740.77 cw(c1094.48,1711.48) 1135.91,1711.48 ; 1123.77,1740.77 cw(c1094.48,1711.48) 1135.91,1711.48
  Bottom Layer w10: R7.1 888.2,1715 1117.65,1715 v8@1122.65,1720
  other v8: 1122.65,1715
MG_PD6: CN1.16 R6.2 | length 573.2
  Bottom Layer w10: CN1.16 R6.2
MG_PD7: CN1.15 U1.61 | length 929.2
  Top Layer w9: CN1.15 192,1488 618.55,1488 644.21,1513.66 U1.61
MG_PD8: CN1.18 U1.62 | length 821
  Top Layer w9: CN1.18 615,1440 672.91,1497.91 U1.62
MG_PD9: CN1.17 U1.63 | length 954.2
  Top Layer w9: CN1.17 188,1392 611.45,1392 701.61,1482.17 U1.63
MG_PD10: CN1.20 U1.64 | length 849.3
  Top Layer w9: CN1.20 605,1340 731.42,1466.42 U1.64
MG_PD11: CN1.19 U1.65 | length 984.5
  Top Layer w9: CN1.19 188,1292 188,1290.67 600.67,1290.67 760.67,1450.67 U1.65
MG_PD12: CN1.22 U1.66 | length 878.6
  Top Layer w9: CN1.22 241.08,1238.92 593.92,1238.92 789.92,1434.92 U1.66
MG_PD13: CN1.21 U1.67 | length 1011
  Top Layer w9: CN1.21 188,1192 592,1192 819.17,1419.17 U1.67
MG_PD14: CN1.24 U1.68 | length 916.6
  Top Layer w9: CN1.24 240.57,1139.43 584.68,1139.43 737,1291.75 ; 729.93,1284.68 848.68,1403.43 U1.68
MG_PD15: CN1.23 U1.69 | length 1039.3
  Top Layer w9: CN1.23 188,1092 577,1092 872.68,1387.68 U1.69
MG_PE0: CN2.36 U1.14 | length 1673.2
  Top Layer w9: U1.14 1328.32,852.74 1489.07,692 2592,692 CN2.36
MG_PE1: CN2.35 U1.15 | length 1506.2
  Top Layer w9: U1.15 1344.07,872.35 1476.42,740 CN2.35
MG_PE2: CN2.34 U1.16 | length 1577.3
  Top Layer w9: U1.16 1359.82,891.96 1459.78,792 2592,792 CN2.34
MG_PE3: CN2.33 U1.17 | length 1410.3
  Top Layer w9: U1.17 1375.57,911.57 1447.13,840 CN2.33
MG_PE8: CN2.20 U1.32 | length 1193.9
  Top Layer w9: U1.32 1773.03,1387.68 1824.85,1439.5 2343.08,1439.5 2395.26,1491.68 2592,1491.68 2592,1492 CN2.20
MG_PE9: CN2.19 U1.33 | length 1093
  Top Layer w9: U1.33 1753.43,1403.43 1813.24,1463.24 2333.24,1463.24 2395,1525 2535,1525 2540,1530 CN2.19
MG_PE12: CN1.5 U1.50 | length 1583.1
  Top Layer w9: v4(1237.2,2017.03) 1281.08,1973.15 U1.50
  Bottom Layer w10: CN1.5 190,2090 270,2090 320,2040 1214.23,2040 v4(1237.2,2017.03)
MG_PE13: CN1.6 U1.51 | length 1412.1
  Top Layer w9: v4(1245,1970) 1265.33,1949.67 U1.51
  Bottom Layer w10: CN1.6 270,2040 301.82,2008.18 1206.82,2008.18 v4(1245,1970)
MG_PE14: CN1.7 U1.52 | length 1479.3
  Top Layer w9: v4(1235,1935) 1249.58,1920.42 U1.52
  Bottom Layer w10: CN1.7 190,1990 270,1990 283.64,1976.36 1193.64,1976.36 v4(1235,1935)
MG_PE15: CN1.8 U1.53 | length 1340
  Top Layer w9: v4(1225,1898) 1233.83,1889.17 U1.53 U1.53@1233.83,1575.28
  Bottom Layer w10: CN1.8 245.06,1945.06 1184.94,1945.06 v4@1232,1898
MG_VR0: C11.1 C20.1 TC3.1 U1.71 | length 279.2
  Top Layer w9: U1.71 1075.18,1356.18 1088.2,1369.2 v7@1088.2,1379.06
  Bottom Layer w30: TC3.1@963.2,1384.06 TC3.1 TC3.1@964.2,1404.06 ; TC3.1@968.5,1410 C11.1 C20.1@1090,1410 ; v7(1090,1375) 1105,1390 C20.1
MG_VREF: C8.1 J1.1 TC2.1 U1.73 | length 332.9
  Top Layer w9: U1.73 1072.57,1324.68 1088.82,1308.43 v7@1088.82,1279.06
  Bottom Layer w30: TC2.1@960,1275 C8.1 v7(1090,1275) ; J1.1 TC2.1@965,1255
NetC19_2: C19.2 Q1.1 R14.1 | length 136.6
  Top Layer w23: C19.2 R14.1@1350,2600 ; C19.2@1357.4,2537.4 Q1.1
NETD1_1: D1.1 R1.2 | length 114.1
  Top Layer w20: D1.1@1613.32,2635 1643.32,2665 R1.2@1715,2665
NetR16_2: R16.2 UP2.3 | length 80
  Bottom Layer w25: UP2.3 R16.2@1810,2495
U5V0_RXD: C7.1 CN3.3 R4.1 | length 211.9
  Top Layer w9: R4.1 C7.1 2192,274.74 CN3.3
U5V0_TXD: C6.1 CN3.4 R5.1 | length 211.9
  Top Layer w9: R5.1 C6.1 2289.8,138.2 CN3.4
UCC1: CJ2.A5 R12.1 | length 104.6
  Top Layer w10: R12.1@559.29,2330 CJ2.A5
UCC2: CJ2.B5 R13.1 | length 121.2
  Top Layer w10: R13.1 441.18,2329.18 CJ2.B5
pads on no net: CJ1.10 CJ1.11 CJ2.A8 CJ2.B8 CN1.3 CN1.4 CN2.3 CN2.42 CN2.43 CN2.44 CN4.6

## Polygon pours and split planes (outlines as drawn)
GND on Top Layer "Top Layer-No Net" (hatched 90Degree grid 10 track 10, remove dead copper, pour order 1000): 20,15 2740,15 2740,2735 20,2735
GND on Bottom Layer "Top Layer-No Net" (hatched 90Degree grid 10 track 10, remove dead copper, pour order 1001): 20,15 2740,15 2740,2735 20,2735

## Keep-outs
Keep-Out Layer:
  lines w11: 850,2755.91 0,2755.91 0,0 2755.91,0 2755.91,2755.91 1160,2755.91

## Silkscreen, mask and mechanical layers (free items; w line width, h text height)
Top Overlay:
  region: 1120,1069.06 1080,1029.06 1160,1029.06
  lines w10: 431.3,95 431.3,250 960,250 960,95 431.3,95 ; 455.05,114.52 455.05,230 940,230 940,114.52 455.05,114.52
  text "+VDD" at 1492.32,2695 h40
  text "DC" at 1880,2659.06 h35
  text "DC" at 2465,2649.06 h35
  text "VDD1" at 1880,2609.06 h35
  text "GND" at 2465,2599.06 h35
  text "GND" at 100,2580 h35
  text "USB_Micro" at 855,2489.06 h35 r90
  text "+3V3" at 2330,2420 h35
  text "GND" at 2735,2405 h35 r90
  text "USB_C-Type" at 297.2,2350 h35 r90
  text "C14" at 2745,2295 h35 r90
  text "+5V" at 300,2230 h35
  text "C13" at 2390,2220 h35
  text "GND" at 59.29,2191.93 h35 r90
  text "C12" at 2735,2190 h35 r90
  text "C11" at 2390,2120 h35
  text "C10" at 2745,2090 h35 r90
  text "E13" at 305,2025 h35
  text "C9" at 2390,2020 h35
  text "C8" at 2741.3,2006.5 h35 r90
  text "E12" at 75,2005 h35 r90
  text "E15" at 305,1925 h35
  text "C7" at 2390,1920 h35
  text "C6" at 2740,1915 h35 r90
  text "E14" at 75,1900 h35 r90
  text "+3V3" at 1410,1890 h35
  text "D0" at 305,1820 h35
  text "C5" at 2390,1820 h35
  text "C4" at 2741.3,1817.99 h35 r90
  text "D1" at 75,1815 h35 r90
  text "D2" at 305,1720 h35
  text "C3" at 2390,1720 h35
  text "C2" at 2741.3,1716.5 h35 r90
  text "D3" at 75,1710 h35 r90
  text "GND" at 2037.2,1700 h35
  text "D4" at 305,1620 h35
  text "C1" at 2390,1620 h35
  text "C0" at 2741.3,1616.5 h35 r90
  text "D5" at 75,1605 h35 r90
  text "D6" at 305,1520 h35
  text "E9" at 2390,1520 h35
  text "E8" at 2745,1515 h35 r90
  text "D7" at 75,1510 h35 r90
  text "D8" at 305,1420 h35
  text "B15" at 2385,1420 h35
  text "B14" at 2735,1410 h35 r90
  text "D9" at 75,1405 h35 r90
  text "D10" at 305,1320 h35
  text "B13" at 2385,1320 h35
  text "B12" at 2745,1305 h35 r90
  text "D11" at 55,1300 h35 r90
  text "D12" at 305,1220 h35
  text "B11" at 2385,1220 h35
  text "D13" at 75,1200 h35 r90
  text "B10" at 2735,1200 h35 r90
  text "D14" at 305,1120 h35
  text "B9" at 2385,1120 h35
  text "B8" at 2740,1115 h35 r90
  text "D15" at 55,1100 h35 r90
  text "B6" at 2740,1030 h35 r90
  text "A0" at 305,1023.5 h35
  text "B7" at 2385,1020 h35
  text "A1" at 75,1015 h35 r90
  text "A2" at 305,925 h35
  text "B5" at 2385,920 h35
  text "B4" at 2740,920 h35 r90
  text "A3" at 75,910 h35 r90
  text "A4" at 305,823.5 h35
  text "E3" at 2385,820 h35
  text "E2" at 2740,815 h35 r90
  text "A5" at 75,810 h35 r90
  text "GND" at 1040,785 h35
  text "A6" at 305,725 h35
  text "E1" at 2385,720 h35
  text "E0" at 2740,720 h35 r90
  text "A7" at 75,715 h35 r90
  text "A8" at 305,625 h35
  text "B3" at 2385,620 h35
  text "B2" at 2740,620 h35 r90
  text "A9" at 75,610 h35 r90
  text "A10" at 305,524.06 h35
  text "+VDD" at 1992,521 h35 r90
  text "GND" at 2092,521 h35 r90
  text "RxD" at 2192,521 h35 r90
  text "TxD" at 2292,521 h35 r90
  text "B1" at 2385,520 h35
  text "B0" at 2740,520 h35 r90
  text "SWOUT" at 1634.29,506.93 h35 r90
  text "A11" at 75,500 h35 r90
  text "SWRST" at 1115,500 h35 r90
  text "SWDIO" at 1339.29,498.43 h35 r90
  text "+VDD_SWD" at 1439.29,498.43 h35 r90
  text "SWCLK" at 1539.29,498.43 h35 r90
  text "GND" at 1224.29,496.93 h35 r90
  text "+VDD" at 2349,426 h35
  text "A12" at 305,425 h35
  text "A13" at 50,395 h35 r90
  text "GND" at 1645,355 h35
  text "A14" at 305,324.53 h35
  text "SWD Connector" at 990,290 h35
  text "A15" at 80,285 h35 r90
  text "2023.07" at 710,280 h40
  text "MG07-01B" at 480.8,141.04 h60
  text "PKT84_LQFP80_USB" at 350,30 h45
  text "UART_CON" at 2425,30 h35
Bottom Overlay:
  text "+VDD_MG2" at 1885,1270 h35
  text "+VDD_MG1" at 1890,1065 h35
Mechanical 1:
  the board outline again, w8.88
Mechanical 18:
  lines w15: 2.2,-0.94 2758.11,-0.94 2758.11,2754.96 2.2,2754.96 2.2,-0.94

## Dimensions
0,0 to 2755.91,0 on Top Overlay
2755.91,0 to 2755.91,2755.91 on Top Overlay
